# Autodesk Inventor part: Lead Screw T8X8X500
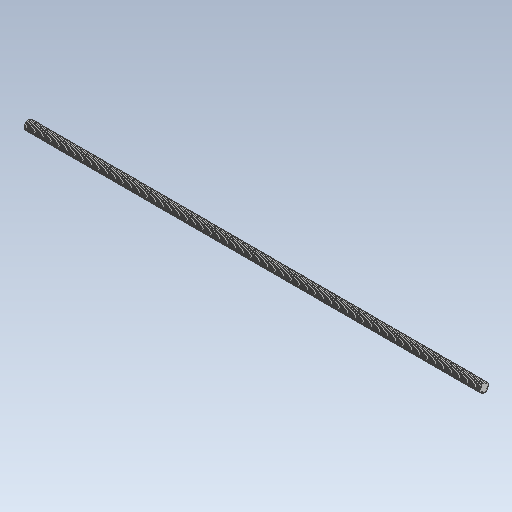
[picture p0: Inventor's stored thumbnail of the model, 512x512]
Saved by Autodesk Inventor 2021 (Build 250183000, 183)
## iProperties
Created: 2026-10
Part Number: Lead Screw T8X8X500
Material: Steel
Document SubType Name: Modeling
Designer: hp
Density: 7.85 g/cm^3
Appearance: Default
Author: hp
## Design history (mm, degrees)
feature "Body5"
body "Solid1"
